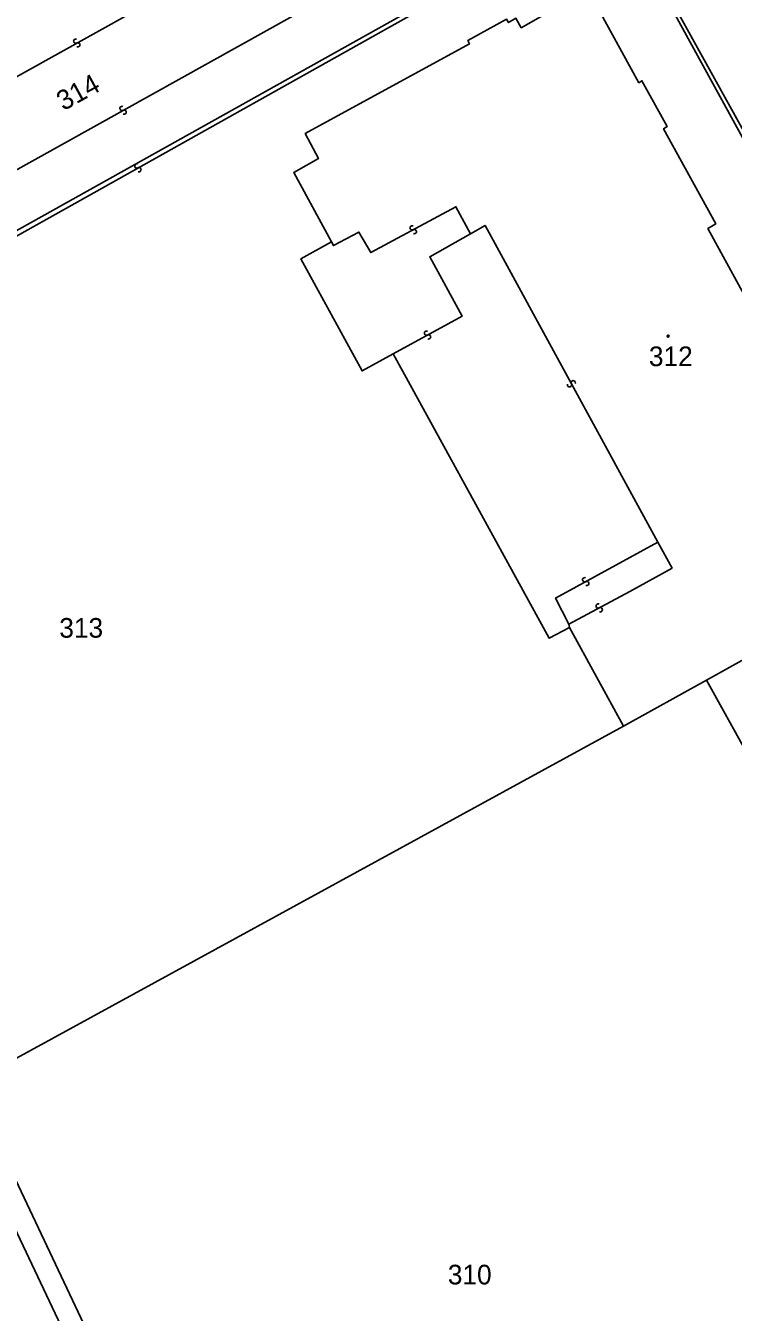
# Model space of a CAD drawing. Extents: x -600391 to -599491, y -1160176 to -1159402.
# Drawn here: x -600117.8 to -600056.6, y -1159912.4 to -1159801.1 of the extents above; entities that cross this region are included whole.
import ezdxf

# ---------------------------------------------------------------- set-up
doc = ezdxf.new("R2010")
doc.units = 0
for name, color, linetype in [('Level 1', 7, 'Continuous'), ('Level 13', 7, 'Continuous'), ('Level 3', 7, 'Continuous'), ('Level 4', 7, 'Continuous'), ('Level 5', 7, 'Continuous')]:
    doc.layers.add(name, color=color, linetype=linetype)

msp = doc.modelspace()

# ---------------------------------------------------------------- linework, layer by layer
at = {"layer": 'Level 1'}
for points in [[(-600149.33, -1159835.93), (-600066.93, -1159789.91)], [(-600066.93, -1159789.91), (-600044.75, -1159829.91)], [(-600091.37, -1159819.77), (-600094.64, -1159813.78), (-600092.5, -1159812.58), (-600093.64, -1159810.41), (-600079.43, -1159802.66), (-600079.57, -1159802.37), (-600076.21, -1159800.53), (-600076.04, -1159800.81), (-600075.4, -1159800.44), (-600074.94, -1159801.26), (-600069.17, -1159797.96), (-600064.75, -1159806.01), (-600064.49, -1159805.85), (-600062.3, -1159809.8), (-600062.62, -1159810), (-600058.11, -1159818.23), (-600058.78, -1159818.63), (-600042.39, -1159848.51)], [(-600086.04, -1159829.46), (-600088.72, -1159830.95), (-600094.02, -1159821.24), (-600091.37, -1159819.77)], [(-600070.77, -1159853.13), (-600072.53, -1159854.05), (-600086.04, -1159829.46)], [(-600066.1, -1159861.67), (-600070.77, -1159853.13)], [(-600058.91, -1159857.7), (-600052.02, -1159853.85)], [(-600066.1, -1159861.67), (-600058.91, -1159857.7)], [(-600058.91, -1159857.7), (-600053.78, -1159866.96), (-600053.18, -1159868.01)], [(-600122.68, -1159892.59), (-600066.1, -1159861.67)], [(-600094.36, -1159952.42), (-600122.68, -1159892.59)]]:
    msp.add_lwpolyline(points, dxfattribs=at)
at = {"layer": 'Level 13'}
for centre, start, end in [((-600113.52, -1159802.42), 66.2377, 298.8277), ((-600113.34, -1159802.74), 246.4522, 118.5502), ((-600109.51, -1159808.24), 66.2388, 298.8288), ((-600109.33, -1159808.56), 246.4533, 118.5513), ((-600108.23, -1159813.22), 66.6203, 298.7183), ((-600108.05, -1159813.54), 246.4058, 118.9958), ((-600084.38, -1159818.57), 65.3756, 297.9656), ((-600084.2, -1159818.89), 245.5901, 117.6881), ((-600083.15, -1159827.68), 65.6476, 298.2376), ((-600082.97, -1159828), 245.862, 117.96), ((-600070.44, -1159831.97), 335.7834, 208.3734), ((-600070.76, -1159832.15), 155.9978, 28.0958), ((-600069.45, -1159849.01), 66.1371, 298.2351), ((-600069.27, -1159849.33), 245.9226, 118.5126), ((-600068.28, -1159851.28), 65.7317, 297.8297), ((-600068.1, -1159851.6), 245.5172, 118.1072)]:
    msp.add_arc(centre, 0.184, start, end, dxfattribs=at)
at = {"layer": 'Level 3'}
for points in [[(-600072.76, -1159779.78), (-600074.27, -1159780.8), (-600152.58, -1159824.35), (-600153.16, -1159824.54), (-600153.99, -1159824.66), (-600154.73, -1159824.62), (-600154.85, -1159824.6)], [(-600069.02, -1159786.29), (-600070.06, -1159786.51), (-600148.78, -1159830.29), (-600149.46, -1159830.71), (-600150.34, -1159831.49), (-600151, -1159832.5)], [(-600149.28, -1159836.42), (-600066.99, -1159790.34), (-600036.77, -1159845.39)], [(-600079.35, -1159819.1), (-600080.6, -1159816.75), (-600087.98, -1159820.71), (-600089, -1159818.94), (-600091.21, -1159820.1), (-600091.37, -1159819.77)], [(-600063.12, -1159845.77), (-600078.08, -1159818.36), (-600079.35, -1159819.1)], [(-600079.35, -1159819.1), (-600082.86, -1159821.07), (-600080.07, -1159826.22), (-600086.04, -1159829.46)], [(-600058.2, -1160028.15), (-600058.36, -1160028.15), (-600059, -1160028.11), (-600059.48, -1160028.02), (-600059.94, -1160027.88), (-600060.54, -1160027.6), (-600093.98, -1159957.52), (-600113.29, -1159916.73), (-600151.13, -1159836.81), (-600151.44, -1159835.9), (-600151.54, -1159834.48), (-600151.24, -1159833.05), (-600151, -1159832.5)], [(-600070.83, -1159852.86), (-600071.97, -1159850.6), (-600066.76, -1159847.74), (-600063.12, -1159845.77)], [(-600070.83, -1159852.86), (-600065.55, -1159850.01), (-600061.89, -1159848), (-600063.12, -1159845.77)], [(-600070.77, -1159853.13), (-600070.83, -1159852.86)]]:
    msp.add_lwpolyline(points, dxfattribs=at)
at = {"layer": 'Level 5'}
for radius in [0.09, 0.0521]:
    msp.add_circle((-600062.23, -1159827.93), radius, dxfattribs=at)

# ---------------------------------------------------------------- texts
at = {"layer": 'Level 4'}
msp.add_text('314', height=1.7, rotation=28.8, dxfattribs=at).set_placement((-600114.58, -1159808.48))
for s, p in [('312', (-600063.89, -1159830.53)), ('313', (-600114.94, -1159854.02)), ('310', (-600081.3, -1159909.96))]:
    msp.add_text(s, height=1.7, dxfattribs=at).set_placement(p)

doc.saveas('drawing.dxf')
